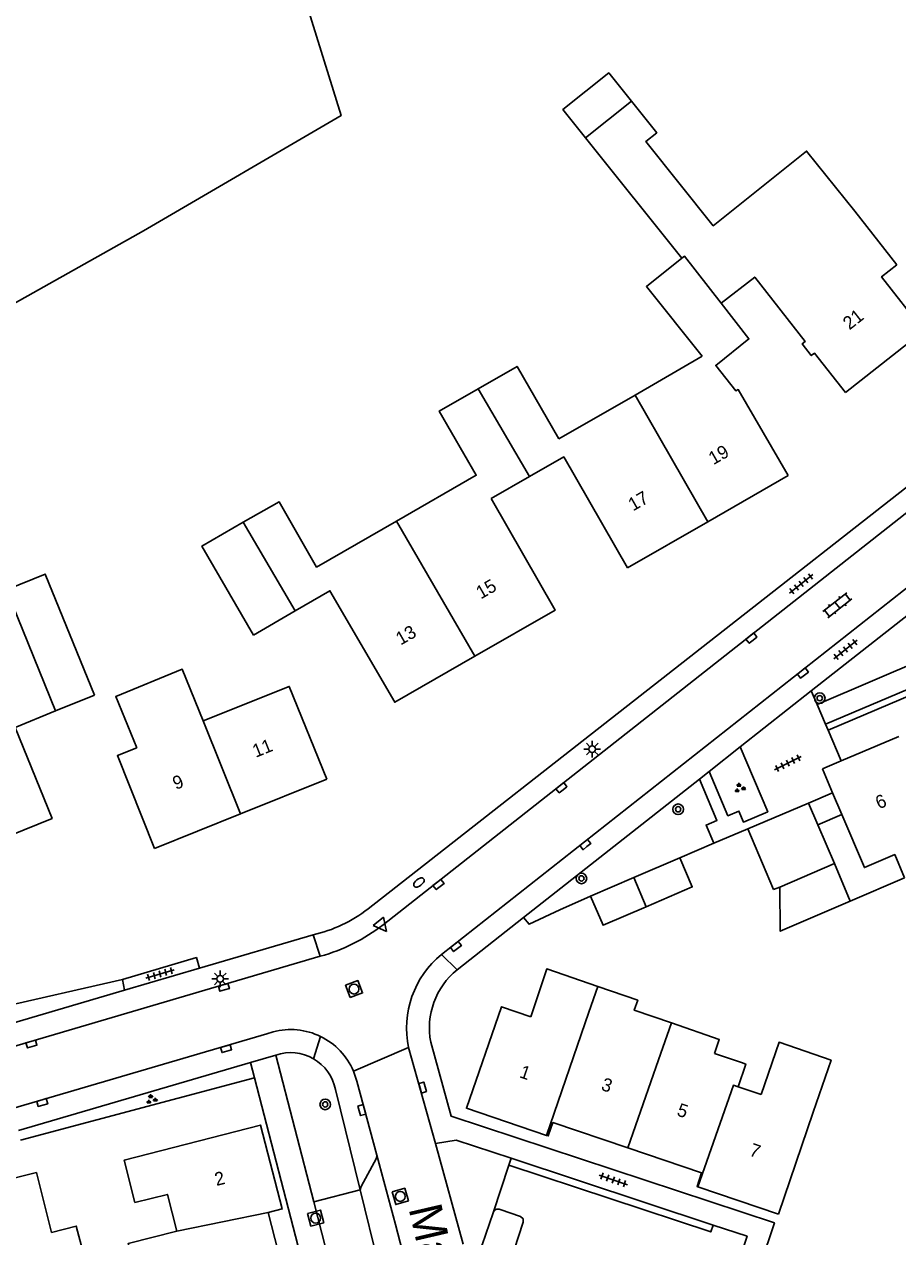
# Model space of a CAD drawing. Extents: x 136000 to 138005, y 398500 to 400500.
# Drawn here: x 137669 to 137735.1, y 398782 to 398873.8 of the extents above; entities that cross this region are included whole.
import ezdxf

# ---------------------------------------------------------------- set-up
doc = ezdxf.new("R2010")
doc.units = 0
for name, color, linetype in [('gg-afsc-erfafscheiding', 7, 'Continuous'), ('gg-afsc-muur', 7, 'Continuous'), ('gg-anno-huisnummerreeks BGT', 7, 'Continuous'), ('gg-anno-openbare ruimte label', 7, 'Continuous'), ('gg-bbg-bijgebouw', 7, 'Continuous'), ('gg-bbg-gedigitaliseerde bebouwing', 7, 'Continuous'), ('gg-bbg-gedigitaliseerde bijgebouw', 7, 'Continuous'), ('gg-bbg-hoofdgebouw', 7, 'Continuous'), ('gg-bbg-luifel en loopbrug', 7, 'Continuous'), ('gg-bbg-tussenscheiding', 7, 'Continuous'), ('gg-knt-bronhoudergrens', 7, 'Continuous'), ('gg-knt-verharding', 7, 'Continuous'), ('gg-knt-verharding nz', 7, 'Continuous'), ('gt-grn-groengrens', 7, 'Continuous'), ('gt-grn-weggrens', 7, 'Continuous'), ('gt-symb-boom', 7, 'Continuous'), ('gt-symb-brandkraan', 7, 'Continuous'), ('gt-symb-groenvak', 7, 'Continuous'), ('gt-symb-klinker verharding', 7, 'Continuous'), ('gt-symb-kolk', 7, 'Continuous'), ('gt-symb-lichtmast', 7, 'Continuous'), ('gt-symb-rioolschacht', 7, 'Continuous'), ('gt-symb-tegel verharding', 7, 'Continuous'), ('gt-symb-waterafsluiter', 7, 'Continuous')]:
    doc.layers.add(name, color=color, linetype=linetype)

# ---------------------------------------------------------------- blocks, each defined once
blk = doc.blocks.new('gt0-WAFSL')
at = {"layer": 'gt-symb-waterafsluiter'}
for p, q in [((-0.5, -0.333), (0, 0.667)), ((0, 0.667), (0.5, -0.333)), ((0.5, -0.333), (-0.5, -0.333))]:
    blk.add_line(p, q, dxfattribs=at)
blk = doc.blocks.new('gt0-RS')
at = {"layer": 'gt-symb-rioolschacht'}
blk.add_lwpolyline([(-0.5, -0.5), (0.5, -0.5), (0.5, 0.5), (-0.5, 0.5)], close=True, dxfattribs=at)
blk.add_circle((0, 0), 0.375, dxfattribs=at)
blk = doc.blocks.new('gt0-KOLK')
at = {"layer": 'gt-symb-kolk'}
blk.add_lwpolyline([(0, 0), (0.375, 0), (0.375, 0.4), (-0.375, 0.4), (-0.375, 0), (0, 0)], dxfattribs=at)
blk = doc.blocks.new('gt0-BOOM')
at = {"layer": 'gt-symb-boom'}
for radius in [0.4, 0.2]:
    blk.add_circle((0, 0), radius, dxfattribs=at)
blk = doc.blocks.new('gt0-BR')
at = {"layer": 'gt-symb-brandkraan'}
for centre, radius, start, end in [((-0.244, 0), 0.206, 107.56694, 252.43307), ((0.599, -2.664), 3, 106.89205, 107.56694), ((0, -0.691), 0.938, 73.10799, 106.89205), ((-0.599, -2.664), 3, 72.43309, 73.10799), ((0.244, 0), 0.206, 287.56695, 72.43309), ((0.599, 2.664), 3, 252.43307, 253.10797), ((0, 0.691), 0.938, 253.10797, 286.89206), ((-0.599, 2.664), 3, 286.89206, 287.56695)]:
    blk.add_arc(centre, radius, start, end, dxfattribs=at)
blk = doc.blocks.new('gt0-GRVAK')
at = {"layer": 'gt-symb-groenvak'}
for p, q in [((-0.11, 0.189), (-0.228, 0.24)), ((-0.182, 0.153), (0.088, 0.153)), ((-0.091, 0.211), (-0.156, 0.322)), ((-0.047, 0.214), (-0.047, 0.393)), ((-0.004, 0.211), (0.061, 0.322)), ((0.015, 0.189), (0.133, 0.24)), ((0.262, -0.052), (0.197, 0.059)), ((0.305, -0.049), (0.305, 0.13)), ((0.349, -0.052), (0.414, 0.059)), ((-0.245, -0.228), (-0.363, -0.177)), ((-0.318, -0.264), (-0.047, -0.264)), ((-0.226, -0.206), (-0.291, -0.095)), ((-0.183, -0.203), (-0.183, -0.024)), ((-0.139, -0.206), (-0.074, -0.095)), ((-0.12, -0.228), (-0.002, -0.177)), ((0.243, -0.074), (0.125, -0.023)), ((0.17, -0.11), (0.441, -0.11)), ((0.368, -0.074), (0.486, -0.023))]:
    blk.add_line(p, q, dxfattribs=at)
blk = doc.blocks.new('gt0-LMAST')
at = {"layer": 'gt-symb-lichtmast'}
for p, q in [((-0.182, 0.173), (-0.447, 0.438)), ((-0.005, 0.246), (-0.005, 0.621)), ((0.172, 0.173), (0.437, 0.438)), ((-0.255, -0.004), (-0.63, -0.004)), ((-0.182, -0.181), (-0.447, -0.446)), ((-0.005, -0.254), (-0.005, -0.629)), ((0.437, -0.446), (0.172, -0.181)), ((0.245, -0.004), (0.62, -0.004))]:
    blk.add_line(p, q, dxfattribs=at)
blk.add_circle((-0.005, -0.004), 0.25, dxfattribs=at)
blk = doc.blocks.new('gt0-TEG1')
at = {"layer": 'gt-symb-tegel verharding'}
for p, q in [((-1.125, 0), (1.125, 0)), ((-0.9, -0.25), (-0.9, 0.25)), ((-0.45, -0.25), (-0.45, 0.25)), ((0, -0.25), (0, 0.25)), ((0.45, -0.25), (0.45, 0.25)), ((0.9, -0.25), (0.9, 0.25))]:
    blk.add_line(p, q, dxfattribs=at)
blk = doc.blocks.new('gt0-KL1')
at = {"layer": 'gt-symb-klinker verharding'}
for p, q in [((-1.15, 0.3), (1.15, 0.3)), ((-1, -0.3), (-1, 0.3)), ((-0.5, 0.3), (-0.5, 0.45)), ((0, -0.3), (0, 0.3)), ((0.5, 0.3), (0.5, 0.45)), ((1, -0.3), (1, 0.3)), ((-1.15, -0.3), (1.15, -0.3)), ((-0.5, -0.45), (-0.5, -0.3)), ((0.5, -0.45), (0.5, -0.3))]:
    blk.add_line(p, q, dxfattribs=at)

msp = doc.modelspace()

# ---------------------------------------------------------------- linework, layer by layer
at = {"layer": 'gg-afsc-erfafscheiding'}
for p, q in [((137662.5, 398798.329), (137676.458, 398801.486)), ((137686.444, 398794.052), (137668.731, 398789.325))]:
    msp.add_line(p, q, dxfattribs=at)
at = {"layer": 'gg-afsc-muur'}
for p, q in [((137723.777, 398812.896), (137721.197, 398811.798)), ((137721.197, 398811.798), (137718.62, 398810.7))]:
    msp.add_line(p, q, dxfattribs=at)
at = {"layer": 'gg-bbg-bijgebouw'}
for p, q in [((137689.517, 398829.393), (137686.37, 398827.56)), ((137671.384, 398821.818), (137674.32, 398823.01)), ((137728.383, 398814.841), (137723.777, 398812.896)), ((137725.722, 398808.289), (137723.777, 398812.896)), ((137718.62, 398810.7), (137715.145, 398809.207)), ((137715.145, 398809.207), (137711.87, 398807.8)), ((137666.32, 398785.96), (137669.94, 398786.87))]:
    msp.add_line(p, q, dxfattribs=at)
at = {"layer": 'gg-bbg-gedigitaliseerde bebouwing'}
for p, q in [((137711.486, 398865.2), (137714.964, 398867.979)), ((137718.773, 398856.082), (137711.486, 398865.2)), ((137731.873, 398859.641), (137735.05, 398855.59)), ((137715.243, 398845.734), (137720.32, 398848.666)), ((137709.482, 398842.408), (137715.243, 398845.734)), ((137729.42, 398817.43), (137730.194, 398815.613)), ((137730.194, 398815.613), (137730.896, 398813.965)), ((137723.291, 398795.2), (137721.25, 398795.889)), ((137724.787, 398792.771), (137723.042, 398793.36)), ((137726.09, 398783.71), (137728.736, 398791.437))]:
    msp.add_line(p, q, dxfattribs=at)
for points in [[(137714.964, 398867.979), (137716.879, 398865.583), (137716.063, 398864.931), (137721.162, 398858.551), (137728.229, 398864.2), (137731.873, 398859.641)], [(137718.773, 398856.082), (137716.1, 398853.946), (137720.32, 398848.666)], [(137709.482, 398842.408), (137706.31, 398847.901), (137703.369, 398846.211)], [(137703.369, 398846.211), (137700.427, 398844.521), (137703.222, 398839.656), (137697.177, 398836.183)], [(137697.177, 398836.183), (137691.133, 398832.711), (137688.292, 398837.656), (137685.585, 398836.101)], [(137682.564, 398821.059), (137680.967, 398824.971), (137675.934, 398822.917), (137677.522, 398819.026)], [(137691.9, 398816.66), (137689.065, 398823.68), (137682.564, 398821.059)], [(137677.522, 398819.026), (137676.063, 398818.438), (137678.88, 398811.41)], [(137730.896, 398813.965), (137732.603, 398809.96), (137734.903, 398810.937), (137735.645, 398809.191)], [(137712.42, 398800.961), (137715.446, 398799.919), (137715.185, 398799.163), (137717.996, 398798.194)], [(137717.996, 398798.194), (137721.614, 398796.948), (137721.25, 398795.889)], [(137724.787, 398792.771), (137726.143, 398796.731), (137730.086, 398795.38), (137728.736, 398791.437)], [(137723.042, 398793.36), (137723.626, 398795.087), (137723.291, 398795.2)], [(137680.555, 398782.44), (137679.844, 398785.221), (137677.39, 398784.61)], [(137681.936, 398776.612), (137678.357, 398775.694), (137676.869, 398781.494), (137680.555, 398782.44)]]:
    msp.add_lwpolyline(points, dxfattribs=at)
at = {"layer": 'gg-bbg-gedigitaliseerde bijgebouw'}
for p, q in [((137728.383, 398814.841), (137729.087, 398813.186)), ((137729.087, 398813.186), (137730.328, 398810.268)), ((137730.328, 398810.268), (137731.538, 398807.423)), ((137725.722, 398808.289), (137726.192, 398808.487)), ((137669.94, 398786.87), (137671.081, 398782.331))]:
    msp.add_line(p, q, dxfattribs=at)
for points in [[(137685.585, 398836.101), (137682.453, 398834.302), (137686.37, 398827.56)], [(137674.32, 398823.01), (137670.595, 398832.183), (137667.675, 398830.997)], [(137718.62, 398810.7), (137719.569, 398808.496), (137716.077, 398806.995)], [(137731.538, 398807.423), (137726.231, 398805.138), (137726.192, 398808.487)], [(137716.077, 398806.995), (137712.819, 398805.595), (137711.87, 398807.8)], [(137671.081, 398782.331), (137672.949, 398782.816), (137673.514, 398780.641)]]:
    msp.add_lwpolyline(points, dxfattribs=at)
at = {"layer": 'gg-bbg-hoofdgebouw'}
for p, q in [((137707.251, 398839.57), (137704.34, 398837.91)), ((137726.827, 398839.628), (137720.755, 398836.135)), ((137720.755, 398836.135), (137714.68, 398832.64)), ((137730.838, 398818.033), (137735.214, 398819.894)), ((137729.42, 398817.43), (137730.838, 398818.033)), ((137691.9, 398816.66), (137685.39, 398814.035)), ((137685.39, 398814.035), (137678.88, 398811.41)), ((137720, 398785.789), (137726.09, 398783.71)), ((137688.868, 398778.4), (137687.47, 398783.85))]:
    msp.add_line(p, q, dxfattribs=at)
for points in [[(137735.05, 398855.59), (137733.9, 398854.69), (137737.11, 398850.59), (137731.172, 398845.934)], [(137731.172, 398845.934), (137728.823, 398848.908), (137728.581, 398848.721), (137727.886, 398849.601), (137728.121, 398849.787), (137724.309, 398854.665), (137721.76, 398852.677)], [(137721.76, 398852.677), (137723.862, 398849.981), (137721.356, 398847.978), (137722.872, 398846.047), (137723.053, 398846.15), (137726.827, 398839.628)], [(137714.68, 398832.64), (137709.843, 398841.048), (137707.251, 398839.57)], [(137704.34, 398837.91), (137709.2, 398829.45), (137703.125, 398825.96)], [(137703.125, 398825.96), (137697.05, 398822.47), (137692.14, 398830.92), (137689.517, 398829.393)], [(137664.61, 398811.04), (137671.11, 398813.68), (137668.31, 398820.57), (137671.384, 398821.818)], [(137707.353, 398798.665), (137708.564, 398802.289), (137712.42, 398800.961)], [(137707.353, 398798.665), (137705.14, 398799.42), (137702.48, 398791.74), (137708.547, 398789.682)], [(137677.39, 398784.61), (137676.57, 398787.81), (137686.9, 398790.47), (137688.54, 398784.12), (137687.47, 398783.85)], [(137708.547, 398789.682), (137708.67, 398789.64), (137709.03, 398790.66), (137714.702, 398788.744)], [(137714.702, 398788.744), (137720.28, 398786.86), (137719.94, 398785.81), (137720, 398785.789)]]:
    msp.add_lwpolyline(points, dxfattribs=at)
at = {"layer": 'gg-bbg-luifel en loopbrug'}
for p, q in [((137729.087, 398813.186), (137730.896, 398813.965)), ((137731.538, 398807.423), (137735.645, 398809.191))]:
    msp.add_line(p, q, dxfattribs=at)
msp.add_lwpolyline([(137714.964, 398867.979), (137713.254, 398870.118), (137709.777, 398867.339), (137711.486, 398865.2)], dxfattribs=at)
at = {"layer": 'gg-bbg-tussenscheiding'}
for p, q in [((137703.369, 398846.211), (137707.251, 398839.57)), ((137715.243, 398845.734), (137720.755, 398836.135)), ((137685.585, 398836.101), (137689.517, 398829.393)), ((137697.177, 398836.183), (137703.125, 398825.96)), ((137667.675, 398830.997), (137671.384, 398821.818)), ((137682.564, 398821.059), (137685.39, 398814.035)), ((137730.328, 398810.268), (137726.192, 398808.487)), ((137715.145, 398809.207), (137716.077, 398806.995)), ((137711.752, 398799.016), (137712.42, 398800.961)), ((137708.547, 398789.682), (137711.752, 398799.016)), ((137717.025, 398795.408), (137717.996, 398798.194)), ((137714.702, 398788.744), (137717.025, 398795.408)), ((137680.555, 398782.44), (137687.47, 398783.85))]:
    msp.add_line(p, q, dxfattribs=at)
for points in [[(137718.773, 398856.082), (137718.977, 398856.245), (137721.76, 398852.677)], [(137720, 398785.789), (137722.689, 398793.479), (137723.042, 398793.36)]]:
    msp.add_lwpolyline(points, dxfattribs=at)
at = {"layer": 'gg-knt-bronhoudergrens'}
msp.add_lwpolyline([(137640.963, 398859.266), (137642.669, 398854.979), (137645.646, 398850.653), (137648.9, 398847.439), (137653.385, 398846.05), (137657.592, 398846.883), (137665.569, 398851.169), (137678.031, 398858.154), (137692.993, 398866.886), (137685.175, 398892.087), (137657.393, 398884.308), (137662.91, 398865.973), (137640.963, 398859.266)], dxfattribs=at)
at = {"layer": 'gg-knt-verharding'}
for p, q in [((137765.325, 398860.104), (137696.173, 398805.626)), ((137700.598, 398803.386), (137757.205, 398847.998)), ((137728.586, 398823.329), (137747.473, 398838.2)), ((137751.66, 398829.63), (137729.85, 398820.355)), ((137728.586, 398823.329), (137723.209, 398819.096)), ((137729.02, 398822.308), (137728.586, 398823.329)), ((137729.654, 398820.815), (137729.02, 398822.308)), ((137729.85, 398820.355), (137729.654, 398820.815)), ((137730.838, 398818.033), (137729.85, 398820.355)), ((137720.846, 398817.236), (137723.209, 398819.096)), ((137706.805, 398806.182), (137720.114, 398816.66)), ((137720.114, 398816.66), (137720.846, 398817.236)), ((137701.769, 398802.217), (137706.805, 398806.182)), ((137682.262, 398802.338), (137690.87, 398804.865)), ((137691.417, 398803.243), (137649.921, 398791.05)), ((137676.599, 398800.676), (137682.262, 398802.338)), ((137676.599, 398800.676), (137676.458, 398801.486)), ((137663.027, 398796.691), (137676.599, 398800.676)), ((137700.148, 398789.075), (137698.101, 398796.329)), ((137686.146, 398795.203), (137688.052, 398795.763)), ((137690.923, 398784.656), (137688.052, 398795.763)), ((137668.563, 398790.062), (137686.146, 398795.203)), ((137686.146, 398795.203), (137686.444, 398794.052)), ((137698.48, 398747.572), (137686.444, 398794.052)), ((137692.56, 398793.16), (137694.436, 398785.564)), ((137702.243, 398781.459), (137700.148, 398789.075)), ((137705.858, 398787.949), (137721.145, 398782.9)), ((137694.436, 398785.564), (137696.52, 398777.128)), ((137697.648, 398758.644), (137690.923, 398784.656))]:
    msp.add_line(p, q, dxfattribs=at)
for points in [[(137695.033, 398806.84), (137763.09, 398860.14), (137763.625, 398860.627)], [(137723.209, 398819.096), (137725.293, 398814.183), (137723.451, 398813.401), (137723.1, 398814.23), (137722.271, 398813.879), (137720.846, 398817.236)], [(137720.114, 398816.66), (137721.442, 398813.527), (137720.613, 398813.175), (137721.197, 398811.798)], [(137676.458, 398801.486), (137682.039, 398803.147), (137682.262, 398802.338)], [(137662.177, 398789.981), (137687.36, 398797.364), (137687.848, 398797.521)], [(137761.274, 398728.544), (137736.96, 398736.9), (137743.49, 398755.64), (137719.38, 398763.98), (137725.79, 398783.06), (137701.316, 398791.144), (137699.778, 398796.748)], [(137695.691, 398788.201), (137694.177, 398793.781), (137694.064, 398794.173), (137693.919, 398794.559)], [(137700.148, 398789.075), (137701.71, 398789.319), (137705.858, 398787.949)], [(137695.691, 398788.201), (137695.66, 398787.972), (137694.518, 398785.815), (137694.436, 398785.564)], [(137703.308, 398780.902), (137703.528, 398781.118), (137703.671, 398781.39), (137704.497, 398783.828)], [(137705.03, 398784.087), (137706.581, 398783.538), (137706.766, 398783.373), (137706.783, 398783.126), (137706.094, 398781.027)], [(137721.145, 398782.9), (137723.72, 398782.05), (137718.715, 398766.996)]]:
    msp.add_lwpolyline(points, dxfattribs=at)
for centre, radius, start, end in [((137688.509, 398815.217), 10.618, 282.84916, 307.9118), ((137687.786, 398816.427), 13.674, 285.39714, 307.8293), ((137705.133, 398797.811), 7.186, 129.12715, 191.90193), ((137705.331, 398797.823), 5.656, 129.03208, 190.95965), ((137689.183, 398792.558), 5.139, 63.96779, 105.05364), ((137689.187, 398792.557), 5.138, 22.92931, 64.01444), ((137689.17, 398792.495), 3.454, 59.99157, 108.8903), ((137689.171, 398792.495), 3.454, 11.09794, 59.99606), ((137704.892, 398783.693), 0.418, 70.75003, 161.08287)]:
    msp.add_arc(centre, radius, start, end, dxfattribs=at)
at = {"layer": 'gg-knt-verharding nz'}
msp.add_lwpolyline([(137698.5, 398777.58), (137697.122, 398782.929), (137695.691, 398788.201)], dxfattribs=at)
at = {"layer": 'gt-grn-groengrens'}
for p, q in [((137729.02, 398822.308), (137750.35, 398831.432)), ((137751.004, 398829.894), (137729.654, 398820.815)), ((137704.497, 398783.828), (137705.686, 398787.428)), ((137705.686, 398787.428), (137705.858, 398787.949)), ((137694.436, 398785.564), (137690.923, 398784.656))]:
    msp.add_line(p, q, dxfattribs=at)
for points in [[(137706.805, 398806.182), (137707.216, 398805.667), (137709.544, 398806.77), (137711.87, 398807.8)], [(137705.686, 398787.428), (137720.973, 398782.379), (137721.145, 398782.9)]]:
    msp.add_lwpolyline(points, dxfattribs=at)
at = {"layer": 'gt-grn-weggrens'}
for p, q in [((137728.383, 398814.841), (137730.194, 398815.613)), ((137691.417, 398803.243), (137690.87, 398804.865)), ((137700.598, 398803.386), (137701.769, 398802.217)), ((137690.898, 398795.486), (137691.438, 398797.176)), ((137693.919, 398794.559), (137698.101, 398796.329))]:
    msp.add_line(p, q, dxfattribs=at)

# ---------------------------------------------------------------- block references
at = {"layer": 'gt-symb-boom'}
for p in [(137729.222, 398822.786), (137718.505, 398814.373), (137711.186, 398809.138), (137691.789, 398792.032)]:
    msp.add_blockref('gt0-BOOM', p, dxfattribs=at)
at = {"layer": 'gt-symb-brandkraan', "rotation": -141.74298312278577}
msp.add_blockref('gt0-BR', (137698.885, 398808.832), dxfattribs=at)
at = {"layer": 'gt-symb-groenvak'}
for p in [(137723.152, 398815.976), (137678.624, 398792.404)]:
    msp.add_blockref('gt0-GRVAK', p, dxfattribs=at)
at = {"layer": 'gt-symb-klinker verharding', "rotation": 38.257016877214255}
msp.add_blockref('gt0-KL1', (137730.553, 398829.821), dxfattribs=at)
at = {"layer": 'gt-symb-kolk'}
for p, rotation in [((137724.178, 398827.179), 38.22155685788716), ((137728.071, 398824.53), 38.22155686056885), ((137709.795, 398815.85), 38.22155685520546), ((137711.598, 398811.546), 38.22155685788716), ((137700.489, 398808.521), 38.22155685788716), ((137701.806, 398803.828), 38.22155685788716), ((137684.178, 398800.699), 16.31519324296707), ((137669.605, 398796.417), 16.31519324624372), ((137684.34, 398796.063), 16.31519324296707), ((137698.968, 398793.252), -74.21205294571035), ((137670.423, 398791.981), 16.31519324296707), ((137694.368, 398791.546), -74.8102128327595)]:
    msp.add_blockref('gt0-KOLK', p, dxfattribs=dict(at, rotation=rotation))
at = {"layer": 'gt-symb-lichtmast'}
for p in [(137712.002, 398818.93), (137683.845, 398801.538)]:
    msp.add_blockref('gt0-LMAST', p, dxfattribs=at)
at = {"layer": 'gt-symb-rioolschacht'}
for p, rotation in [((137693.97, 398800.762), 20.35496118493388), ((137697.469, 398785.065), -74.21205294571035), ((137691.064, 398783.424), -75.51896562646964)]:
    msp.add_blockref('gt0-RS', p, dxfattribs=dict(at, rotation=rotation))
at = {"layer": 'gt-symb-tegel verharding'}
for p, rotation in [((137727.82, 398831.437), 38.257016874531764), ((137731.174, 398826.466), 38.257016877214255), ((137726.805, 398817.861), 26.283312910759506), ((137679.282, 398801.911), 16.386305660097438), ((137713.596, 398786.315), -18.670583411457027)]:
    msp.add_blockref('gt0-TEG1', p, dxfattribs=dict(at, rotation=rotation))
at = {"layer": 'gt-symb-waterafsluiter', "rotation": -141.74298311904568}
msp.add_blockref('gt0-WAFSL', (137696.02, 398805.633), dxfattribs=at)

# ---------------------------------------------------------------- texts
at = {"layer": 'gg-anno-huisnummerreeks BGT'}
for s, rotation, p in [('21', 38.1, (137731.472, 398850.618)), ('19', 29.9, (137721.168, 398840.412)), ('17', 29.9, (137715.089, 398836.914)), ('15', 29.9, (137703.571, 398830.252)), ('13', 29.9, (137697.496, 398826.762)), ('11', 22, (137686.529, 398818.267)), ('9', 22, (137680.487, 398815.831)), ('6', 23, (137733.7, 398814.36)), ('1', 341.3, (137706.426, 398794.097)), ('3', 341.3, (137712.608, 398793.146)), ('5', 341.3, (137718.341, 398791.21)), ('7', 341.1, (137723.825, 398788.182)), ('2', 14.5, (137683.561, 398785.849))]:
    msp.add_text(s, height=1, rotation=rotation, dxfattribs=at).set_placement(p)
at = {"layer": 'gg-anno-openbare ruimte label'}
msp.add_text('Mariahof', height=2.5, rotation=283.1, dxfattribs=at).set_placement((137698.09, 398784.161))

doc.saveas('drawing.dxf')
